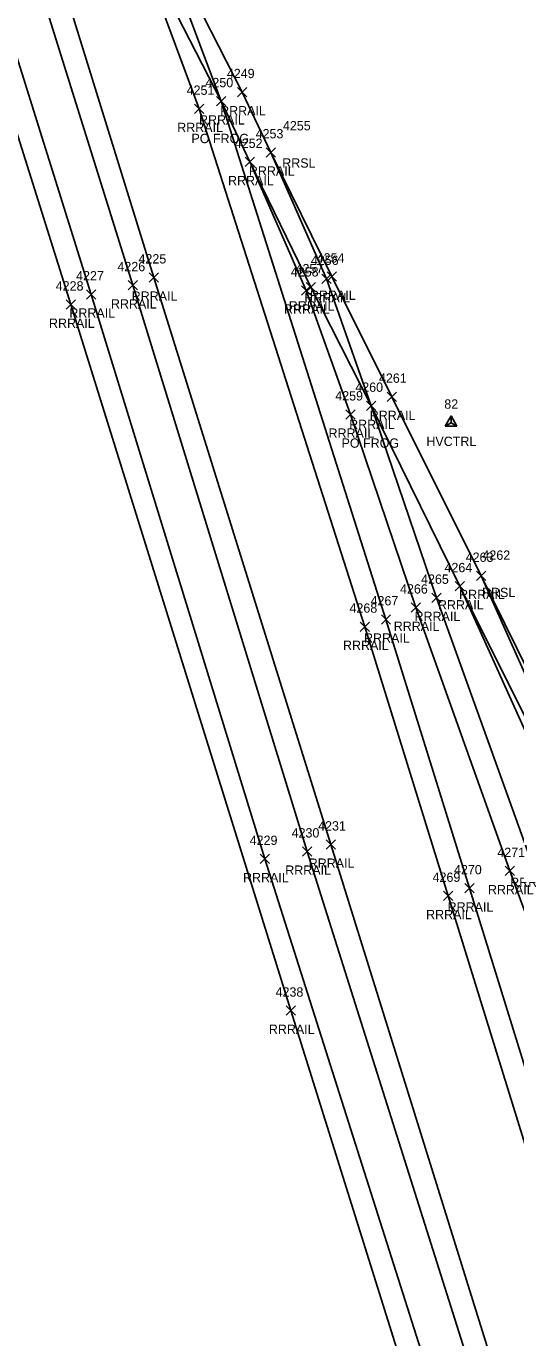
# Model space of a CAD drawing. Extents: x 1462668 to 1465147, y 550359 to 557351.
# Drawn here: x 1463645.3 to 1463750.3, y 555430.8 to 555712.3 of the extents above; entities that cross this region are included whole.
import ezdxf

# ---------------------------------------------------------------- set-up
doc = ezdxf.new("R2010")
doc.units = 0
for name, color, linetype in [('C_A', 7, 'Continuous'), ('C_I', 7, 'Continuous'), ('CPSM', 7, 'Continuous'), ('R_A', 7, 'Continuous'), ('R_C', 7, 'Continuous'), ('R_I', 7, 'Continuous'), ('R_TIC', 7, 'Continuous'), ('RR', 7, 'Continuous')]:
    doc.layers.add(name, color=color, linetype=linetype)

msp = doc.modelspace()

# ---------------------------------------------------------------- linework, layer by layer
at = {"layer": 'CPSM'}
for p, q in [((1463735.16, 555626.47), (1463736.41, 555628.64)), ((1463735.16, 555626.47), (1463736.41, 555627.19)), ((1463735.16, 555626.47), (1463737.66, 555626.47)), ((1463737.66, 555626.47), (1463736.41, 555628.64)), ((1463736.41, 555627.19), (1463736.41, 555628.64)), ((1463736.41, 555627.19), (1463736.41, 555627.19)), ((1463736.41, 555627.19), (1463737.66, 555626.47))]:
    msp.add_line(p, q, dxfattribs=at)
at = {"layer": 'R_TIC'}
for points in [[(1463690.6, 555697.13), (1463692.6, 555699.13)], [(1463692.6, 555697.13), (1463690.6, 555699.13)], [(1463686.08, 555695.18), (1463688.08, 555697.18)], [(1463688.08, 555695.18), (1463686.08, 555697.18)], [(1463686.08, 555695.18), (1463688.08, 555697.18)], [(1463688.08, 555695.18), (1463686.08, 555697.18)], [(1463681.4, 555693.55), (1463683.4, 555695.55)], [(1463683.4, 555693.55), (1463681.4, 555695.55)], [(1463696.76, 555684.2), (1463698.76, 555686.2)], [(1463698.76, 555684.2), (1463696.76, 555686.2)], [(1463696.76, 555684.2), (1463698.76, 555686.2)], [(1463698.76, 555684.2), (1463696.76, 555686.2)], [(1463692.29, 555682.15), (1463694.29, 555684.15)], [(1463694.29, 555682.15), (1463692.29, 555684.15)], [(1463692.29, 555682.15), (1463694.29, 555684.15)], [(1463694.29, 555682.15), (1463692.29, 555684.15)], [(1463667.19, 555655.69), (1463669.19, 555657.69)], [(1463669.19, 555655.69), (1463667.19, 555657.69)], [(1463671.64, 555657.35), (1463673.64, 555659.35)], [(1463673.64, 555657.35), (1463671.64, 555659.35)], [(1463705.32, 555655.25), (1463707.32, 555657.25)], [(1463707.32, 555655.25), (1463705.32, 555657.25)], [(1463708.66, 555657.04), (1463710.66, 555659.04)], [(1463710.66, 555657.04), (1463708.66, 555659.04)], [(1463709.85, 555657.55), (1463711.85, 555659.55)], [(1463711.85, 555657.55), (1463709.85, 555659.55)], [(1463658.27, 555653.72), (1463660.27, 555655.72)], [(1463660.27, 555653.72), (1463658.27, 555655.72)], [(1463704.3, 555654.56), (1463706.3, 555656.56)], [(1463706.3, 555654.56), (1463704.3, 555656.56)], [(1463653.9, 555651.54), (1463655.9, 555653.54)], [(1463655.9, 555651.54), (1463653.9, 555653.54)], [(1463718.26, 555629.81), (1463720.26, 555631.81)], [(1463720.26, 555629.81), (1463718.26, 555631.81)], [(1463718.26, 555629.81), (1463720.26, 555631.81)], [(1463720.26, 555629.81), (1463718.26, 555631.81)], [(1463722.68, 555631.75), (1463724.68, 555633.75)], [(1463724.68, 555631.75), (1463722.68, 555633.75)], [(1463713.84, 555627.95), (1463715.84, 555629.95)], [(1463715.84, 555627.95), (1463713.84, 555629.95)], [(1463741.84, 555593.32), (1463743.84, 555595.32)], [(1463743.84, 555593.32), (1463741.84, 555595.32)], [(1463741.84, 555593.32), (1463743.84, 555595.32)], [(1463743.84, 555593.32), (1463741.84, 555595.32)], [(1463737.3, 555591.1), (1463739.3, 555593.1)], [(1463739.3, 555591.1), (1463737.3, 555593.1)], [(1463737.3, 555591.1), (1463739.3, 555593.1)], [(1463739.3, 555591.1), (1463737.3, 555593.1)], [(1463732.28, 555588.61), (1463734.28, 555590.61)], [(1463734.28, 555588.61), (1463732.28, 555590.61)], [(1463727.82, 555586.51), (1463729.82, 555588.51)], [(1463729.82, 555586.51), (1463727.82, 555588.51)], [(1463716.94, 555582.41), (1463718.94, 555584.41)], [(1463718.94, 555582.41), (1463716.94, 555584.41)], [(1463721.45, 555583.97), (1463723.45, 555585.97)], [(1463723.45, 555583.97), (1463721.45, 555585.97)], [(1463704.56, 555534.16), (1463706.56, 555536.16)], [(1463706.56, 555534.16), (1463704.56, 555536.16)], [(1463709.59, 555535.66), (1463711.59, 555537.66)], [(1463711.59, 555535.66), (1463709.59, 555537.66)], [(1463695.5, 555532.57), (1463697.5, 555534.57)], [(1463697.5, 555532.57), (1463695.5, 555534.57)], [(1463748.02, 555529.98), (1463750.02, 555531.98)], [(1463750.02, 555529.98), (1463748.02, 555531.98)], [(1463739.37, 555526.27), (1463741.37, 555528.27)], [(1463741.37, 555526.27), (1463739.37, 555528.27)], [(1463734.76, 555524.64), (1463736.76, 555526.64)], [(1463736.76, 555524.64), (1463734.76, 555526.64)], [(1463701.04, 555500.01), (1463703.04, 555502.01)], [(1463703.04, 555500.01), (1463701.04, 555502.01)]]:
    msp.add_lwpolyline(points, dxfattribs=at)
at = {"layer": 'RR'}
for points in [[(1463452.29, 556399.95), (1463497.45, 556252.55), (1463536.87, 556125.13), (1463559.44, 556051.72), (1463609.03, 555892.1), (1463628.98, 555828.76), (1463638.23, 555801.69), (1463650.08, 555771.85), (1463660.17, 555749.93), (1463672.27, 555721.97), (1463682.4, 555694.55), (1463717.94, 555583.41), (1463735.76, 555525.64), (1463763.54, 555435.87), (1463784.43, 555367.81), (1463820.27, 555252.31), (1463843.81, 555175.84), (1463843.97, 555175.21), (1463873.04, 555081.28), (1463903.09, 554986.35)], [(1463457.08, 556400.94), (1463502.23, 556254.01), (1463520.47, 556194.57), (1463541.51, 556126.54), (1463564.15, 556052.98), (1463586.06, 555983.65), (1463613.76, 555893.64), (1463633.52, 555829.96), (1463642.44, 555804.5), (1463654.17, 555774.55), (1463664.49, 555752.05), (1463676.6, 555724.22), (1463687.08, 555696.18), (1463722.45, 555584.97), (1463740.37, 555527.27), (1463768.14, 555437.45), (1463788.82, 555369.5), (1463824.75, 555254.42), (1463848.38, 555177.53), (1463848.44, 555177), (1463877.95, 555082.45), (1463907.74, 554987.88)], [(1463442.74, 556395.94), (1463488.6, 556249.11), (1463529.74, 556117.02), (1463572.82, 555978.5), (1463585.63, 555937.65), (1463596.03, 555904.23), (1463633.49, 555784.66), (1463672.64, 555658.35), (1463710.59, 555536.66), (1463747.52, 555418.1), (1463780.06, 555313.88), (1463826.09, 555167.8), (1463825.99, 555167.57), (1463854.77, 555075.73), (1463884.96, 554978.2)], [(1463438.37, 556393.48), (1463483.91, 556247.77), (1463525.3, 556114.77), (1463568.13, 555976.96), (1463580.9, 555936.2), (1463591.21, 555903.11), (1463628.7, 555782.9), (1463668.19, 555656.69), (1463705.56, 555535.16), (1463742.77, 555417.12), (1463775.39, 555312.32), (1463821.31, 555166.17), (1463821.55, 555165.37), (1463850.06, 555074.38), (1463880.04, 554977.58)], [(1463572.82, 555978.5), (1463584.06, 555937.35), (1463591.21, 555903.11), (1463598.42, 555867.93), (1463607.06, 555827.71), (1463619.3, 555782.42), (1463659.27, 555654.72), (1463696.5, 555533.57), (1463734.29, 555414.51), (1463767.42, 555309.25), (1463798.97, 555209.76)], [(1463568.13, 555976.96), (1463579.35, 555935.43), (1463586.63, 555901.93), (1463593.51, 555867.09), (1463602.3, 555826.27), (1463614.8, 555780.19), (1463654.9, 555652.54), (1463702.04, 555501.01), (1463726.18, 555423.83), (1463744.37, 555366.2), (1463775.2, 555267.76), (1463794.28, 555208.18)], [(1463660.17, 555749.93), (1463673.57, 555722.6), (1463687.08, 555696.18), (1463693.29, 555683.15), (1463705.3, 555655.56), (1463714.84, 555628.95), (1463728.82, 555587.51), (1463749.02, 555530.98), (1463781.53, 555442.53), (1463805.95, 555375.13), (1463826.64, 555318.26), (1463847.08, 555263.8), (1463864.63, 555219.02), (1463880.36, 555179.69), (1463893.23, 555148.43), (1463922.16, 555080.4)], [(1463664.49, 555752.05), (1463678.11, 555724.67), (1463691.6, 555698.13), (1463697.76, 555685.2), (1463709.66, 555658.04), (1463719.26, 555630.81), (1463733.28, 555589.61), (1463753.79, 555532.54), (1463786.2, 555444.26), (1463810.8, 555376.27), (1463831.06, 555320.63), (1463851.61, 555265.5), (1463869.18, 555221.12), (1463884.86, 555181.45), (1463897.64, 555150.83), (1463926.6, 555082.57)], [(1463697.76, 555685.2), (1463710.85, 555658.55), (1463723.68, 555632.75), (1463742.84, 555594.32), (1463759.37, 555557.32), (1463773.18, 555522.79), (1463781.07, 555501.92), (1463799.76, 555451.53), (1463820.57, 555395.15), (1463845.63, 555328.97), (1463867.69, 555270.13), (1463883.9, 555226.62), (1463898.57, 555187.55), (1463911.56, 555155.2), (1463943.25, 555082.83)], [(1463693.29, 555683.15), (1463706.32, 555656.25), (1463719.26, 555630.81), (1463738.3, 555592.1), (1463754.94, 555555.21), (1463768.77, 555520.44), (1463776.2, 555501.13), (1463795.15, 555449.79), (1463815.91, 555394.26), (1463841.16, 555327.36), (1463863.25, 555268.2), (1463879.34, 555225.14), (1463894.04, 555185.93), (1463907.43, 555152.62), (1463938.93, 555080.65)], [(1463742.84, 555594.32), (1463760.75, 555558.08), (1463777.72, 555524.42), (1463787.9, 555504.12), (1463799.93, 555481.15), (1463819.96, 555441.9), (1463835.07, 555412.08), (1463853.2, 555376.47), (1463903.47, 555275.99), (1463977.02, 555121.98), (1463987.14, 555099.63), (1463989.7, 555093.34), (1464001.63, 555067.05), (1464016.17, 555038.45), (1464031.3, 555009.85), (1464051, 554966.45), (1464070.2, 554918.71), (1464087.5, 554872.76), (1464098.32, 554844.67), (1464105, 554826.89), (1464134.6, 554748.85), (1464158.08, 554686.95), (1464184.75, 554615.39)], [(1463738.3, 555592.1), (1463756.39, 555555.83), (1463773.18, 555522.79), (1463783.39, 555502.23), (1463795.59, 555478.87), (1463816.57, 555437.48), (1463830.94, 555409.51), (1463848.79, 555374.55), (1463899.55, 555272.92), (1463973.09, 555118.65), (1463983.69, 555094.87), (1463985.23, 555091.39), (1463997, 555065), (1464011.61, 555036.65), (1464026.5, 555008.18), (1464046.45, 554964.72), (1464065.66, 554916.67), (1464082.8, 554871.21), (1464093.87, 554842.43), (1464100.4, 554825.05), (1464129.92, 554747.44), (1464153.38, 554685.33), (1464180.48, 554613.64)]]:
    msp.add_lwpolyline(points, dxfattribs=at)

# ---------------------------------------------------------------- texts
at = {"layer": 'C_A'}
msp.add_text('HVCTRL', height=2, dxfattribs=at).set_placement((1463731.11, 555622.19))
at = {"layer": 'C_I'}
msp.add_text('82', height=2, dxfattribs=at).set_placement((1463734.95, 555630.19))
at = {"layer": 'R_A'}
for s, p in [('RRRAIL', (1463686.89, 555693.13)), ('RRRAIL', (1463677.69, 555689.55)), ('RRRAIL', (1463682.37, 555691.18)), ('RRRAIL', (1463682.37, 555691.18)), ('RRRAIL', (1463693.05, 555680.2)), ('RRRAIL', (1463693.05, 555680.2)), ('RRSL', (1463700.21, 555681.92)), ('RRRAIL', (1463688.58, 555678.15)), ('RRRAIL', (1463688.58, 555678.15)), ('RRRAIL', (1463667.93, 555653.35)), ('RRRAIL', (1463704.95, 555653.04)), ('RRRAIL', (1463706.14, 555653.55)), ('RRRAIL', (1463654.56, 555649.72)), ('RRRAIL', (1463663.48, 555651.69)), ('RRRAIL', (1463700.59, 555650.56)), ('RRRAIL', (1463701.61, 555651.25)), ('RRRAIL', (1463650.19, 555647.54)), ('RRRAIL', (1463718.97, 555627.75)), ('RRRAIL', (1463710.13, 555623.95)), ('RRRAIL', (1463714.55, 555625.81)), ('RRRAIL', (1463714.55, 555625.81)), ('RRRAIL', (1463738.13, 555589.32)), ('RRRAIL', (1463738.13, 555589.32)), ('RRSL', (1463743.04, 555589.76)), ('RRRAIL', (1463728.57, 555584.61)), ('RRRAIL', (1463733.59, 555587.1)), ('RRRAIL', (1463733.59, 555587.1)), ('RRRAIL', (1463724.11, 555582.51)), ('RRRAIL', (1463717.74, 555579.97)), ('RRRAIL', (1463713.23, 555578.41)), ('RRRAIL', (1463705.88, 555531.66)), ('RRRAIL', (1463691.79, 555528.57)), ('RRRAIL', (1463700.85, 555530.16)), ('RRRAIL', (1463744.31, 555525.98)), ('RRRAIL', (1463749.08, 555527.54)), ('RRRAIL', (1463731.05, 555520.64)), ('RRRAIL', (1463735.66, 555522.27)), ('RRRAIL', (1463697.33, 555496.01))]:
    msp.add_text(s, height=2, dxfattribs=at).set_placement(p)
at = {"layer": 'R_C'}
for p in [(1463680.74, 555687.18), (1463680.74, 555687.18), (1463712.92, 555621.81), (1463712.92, 555621.81)]:
    msp.add_text('PO FROG', height=2, dxfattribs=at).set_placement(p)
at = {"layer": 'R_I'}
for s, p in [('4249', (1463688.33, 555701.13)), ('4251', (1463679.71, 555697.55)), ('4250', (1463683.74, 555699.18)), ('4250', (1463683.74, 555699.18)), ('4255', (1463700.35, 555689.92)), ('4252', (1463690.03, 555686.15)), ('4252', (1463690.03, 555686.15)), ('4253', (1463694.5, 555688.2)), ('4253', (1463694.5, 555688.2)), ('4225', (1463669.38, 555661.35)), ('4256', (1463706.34, 555661.04)), ('4254', (1463707.59, 555661.55)), ('4227', (1463656.01, 555657.72)), ('4226', (1463664.87, 555659.69)), ('4258', (1463702.04, 555658.56)), ('4257', (1463703.06, 555659.25)), ('4228', (1463651.64, 555655.54)), ('4261', (1463720.94, 555635.75)), ('4260', (1463715.87, 555633.81)), ('4260', (1463715.87, 555633.81)), ('4259', (1463711.57, 555631.95)), ('4263', (1463739.54, 555597.32)), ('4263', (1463739.54, 555597.32)), ('4262', (1463743.13, 555597.76)), ('4264', (1463734.99, 555595.1)), ('4264', (1463734.99, 555595.1)), ('4266', (1463725.46, 555590.51)), ('4265', (1463729.97, 555592.61)), ('4267', (1463719.14, 555587.97)), ('4268', (1463714.63, 555586.41)), ('4231', (1463707.9, 555539.66)), ('4230', (1463702.21, 555538.16)), ('4229', (1463693.23, 555536.57)), ('4271', (1463746.32, 555533.98)), ('4269', (1463732.44, 555528.64)), ('4270', (1463737.03, 555530.27)), ('4238', (1463698.78, 555504.01))]:
    msp.add_text(s, height=2, dxfattribs=at).set_placement(p)

doc.saveas('drawing.dxf')
